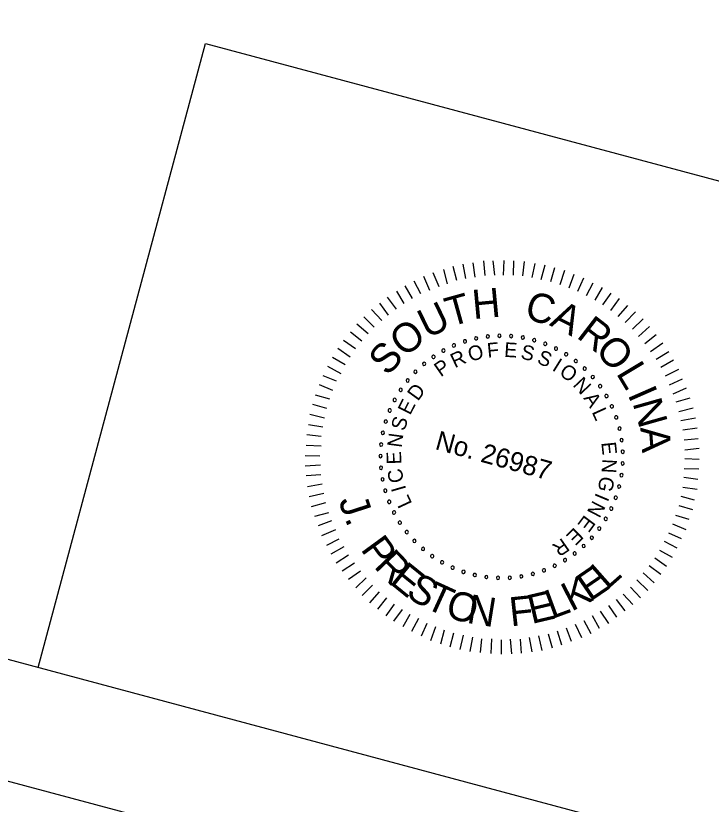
# Model space of a CAD drawing. Extents: x 1970764 to 1971371, y 795839 to 796297.
# Drawn here: x 1971092.8 to 1971137.2, y 795889.2 to 795939.6 of the extents above; entities that cross this region are included whole.
import ezdxf

# ---------------------------------------------------------------- set-up
doc = ezdxf.new("R2010")
doc.units = 0
for name, color, linetype in [('BR_BORDER LINES', 7, 'Continuous'), ('BR_TEXT', 7, 'Continuous'), ('Level 31', 7, 'Continuous')]:
    doc.layers.add(name, color=color, linetype=linetype)

msp = doc.modelspace()

# ---------------------------------------------------------------- linework, layer by layer
at = {"layer": 'BR_BORDER LINES'}
for p, q in [((1970792.881, 795978.637), (1971280.696, 795848.052)), ((1971094.278, 795897.955), (1971104.945, 795937.803)), ((1971104.945, 795937.803), (1971182.685, 795916.993))]:
    msp.add_line(p, q, dxfattribs=at)
at = {"layer": 'BR_TEXT'}
for p, q in [((1971120.999, 795922.662), (1971120.769, 795923.567)), ((1971121.568, 795922.786), (1971121.406, 795923.699)), ((1971122.17, 795922.886), (1971122.045, 795923.789)), ((1971122.796, 795922.98), (1971122.72, 795923.91)), ((1971123.419, 795923.009), (1971123.326, 795923.929)), ((1971123.981, 795923.013), (1971124.026, 795923.949)), ((1971124.618, 795922.997), (1971124.643, 795923.912)), ((1971125.219, 795922.951), (1971125.326, 795923.869)), ((1971125.807, 795922.856), (1971125.988, 795923.753)), ((1971126.388, 795922.735), (1971126.646, 795923.665)), ((1971127.006, 795922.604), (1971127.253, 795923.497)), ((1971119.862, 795922.269), (1971119.494, 795923.159)), ((1971120.395, 795922.456), (1971120.164, 795923.361)), ((1971127.604, 795922.399), (1971127.886, 795923.322)), ((1971128.176, 795922.2), (1971128.482, 795923.064)), ((1971118.704, 795921.801), (1971118.275, 795922.614)), ((1971119.276, 795922.031), (1971118.891, 795922.912)), ((1971128.718, 795921.984), (1971129.11, 795922.823)), ((1971129.27, 795921.71), (1971129.705, 795922.512)), ((1971118.173, 795921.521), (1971117.703, 795922.332)), ((1971129.824, 795921.397), (1971130.292, 795922.216)), ((1971117.14, 795920.831), (1971116.575, 795921.589)), ((1971117.627, 795921.191), (1971117.162, 795921.974)), ((1971130.317, 795921.101), (1971130.857, 795921.846)), ((1971130.836, 795920.756), (1971131.38, 795921.515)), ((1971116.635, 795920.45), (1971116.073, 795921.22)), ((1971131.288, 795920.364), (1971131.908, 795921.061)), ((1971116.208, 795920.115), (1971115.556, 795920.802)), ((1971131.741, 795919.972), (1971132.41, 795920.655)), ((1971115.712, 795919.677), (1971115.058, 795920.352)), ((1971132.215, 795919.56), (1971132.89, 795920.215)), ((1971115.327, 795919.25), (1971114.618, 795919.873)), ((1971132.603, 795919.08), (1971133.303, 795919.727)), ((1971114.931, 795918.785), (1971114.2, 795919.374)), ((1971133.001, 795918.635), (1971133.724, 795919.223)), ((1971114.529, 795918.295), (1971113.771, 795918.838)), ((1971133.369, 795918.133), (1971134.151, 795918.692)), ((1971114.194, 795917.76), (1971113.39, 795918.329)), ((1971133.729, 795917.646), (1971134.527, 795918.12)), ((1971113.876, 795917.287), (1971113.054, 795917.741)), ((1971134.028, 795917.136), (1971134.824, 795917.597)), ((1971113.609, 795916.706), (1971112.765, 795917.18)), ((1971134.314, 795916.576), (1971135.165, 795916.995)), ((1971113.316, 795916.226), (1971112.466, 795916.582)), ((1971113.089, 795915.648), (1971112.224, 795915.994)), ((1971134.584, 795916.007), (1971135.408, 795916.38)), ((1971134.798, 795915.427), (1971135.663, 795915.802)), ((1971112.894, 795915.088), (1971111.964, 795915.345)), ((1971135.003, 795914.916), (1971135.891, 795915.178)), ((1971112.705, 795914.499), (1971111.799, 795914.75)), ((1971135.179, 795914.294), (1971136.075, 795914.54)), ((1971112.558, 795913.872), (1971111.621, 795914.104)), ((1971112.441, 795913.303), (1971111.517, 795913.439)), ((1971135.302, 795913.725), (1971136.243, 795913.892)), ((1971135.415, 795913.12), (1971136.334, 795913.253)), ((1971112.338, 795912.691), (1971111.419, 795912.798)), ((1971135.509, 795912.493), (1971136.413, 795912.576)), ((1971112.329, 795912.079), (1971111.369, 795912.131)), ((1971135.546, 795911.855), (1971136.466, 795911.947)), ((1971112.26, 795911.443), (1971111.321, 795911.476)), ((1971135.551, 795911.293), (1971136.477, 795911.263)), ((1971112.286, 795910.862), (1971111.308, 795910.799)), ((1971135.507, 795910.65), (1971136.437, 795910.633)), ((1971112.305, 795910.256), (1971111.376, 795910.179)), ((1971135.487, 795910.095), (1971136.373, 795909.97)), ((1971112.406, 795909.654), (1971111.465, 795909.487)), ((1971135.421, 795909.472), (1971136.33, 795909.327)), ((1971112.51, 795909.064), (1971111.572, 795908.856)), ((1971135.288, 795908.894), (1971136.157, 795908.654)), ((1971112.611, 795908.462), (1971111.703, 795908.219)), ((1971135.161, 795908.289), (1971136.041, 795908.045)), ((1971112.811, 795907.832), (1971111.902, 795907.589)), ((1971134.952, 795907.679), (1971135.814, 795907.413)), ((1971113.004, 795907.324), (1971112.137, 795906.99)), ((1971134.772, 795907.127), (1971135.623, 795906.772)), ((1971113.242, 795906.738), (1971112.365, 795906.366)), ((1971134.509, 795906.559), (1971135.327, 795906.186)), ((1971113.469, 795906.154), (1971112.671, 795905.734)), ((1971134.227, 795906.023), (1971135.041, 795905.584)), ((1971113.787, 795905.665), (1971112.961, 795905.186)), ((1971133.935, 795905.449), (1971134.745, 795904.998)), ((1971114.089, 795905.114), (1971113.296, 795904.613)), ((1971133.638, 795904.957), (1971134.384, 795904.417)), ((1971114.458, 795904.612), (1971113.686, 795904.091)), ((1971133.285, 795904.453), (1971134.018, 795903.917)), ((1971114.839, 795904.106), (1971114.076, 795903.569)), ((1971132.89, 795903.988), (1971133.599, 795903.365)), ((1971115.2, 795903.672), (1971114.544, 795903.039)), ((1971132.485, 795903.539), (1971133.196, 795902.875)), ((1971115.619, 795903.209), (1971114.956, 795902.551)), ((1971132.077, 795903.078), (1971132.719, 795902.406)), ((1971116.036, 795902.786), (1971115.428, 795902.086)), ((1971116.501, 795902.391), (1971115.931, 795901.68)), ((1971131.606, 795902.634), (1971132.236, 795901.965)), ((1971116.991, 795901.988), (1971116.454, 795901.255)), ((1971130.686, 795901.913), (1971131.198, 795901.157)), ((1971131.168, 795902.301), (1971131.727, 795901.572)), ((1971117.514, 795901.657), (1971116.957, 795900.902)), ((1971117.987, 795901.339), (1971117.551, 795900.538)), ((1971130.156, 795901.539), (1971130.673, 795900.755)), ((1971118.555, 795901.075), (1971118.096, 795900.24)), ((1971129.114, 795900.959), (1971129.548, 795900.118)), ((1971129.643, 795901.28), (1971130.082, 795900.451)), ((1971119.08, 795900.756), (1971118.711, 795899.95)), ((1971119.634, 795900.536), (1971119.325, 795899.66)), ((1971120.195, 795900.341), (1971119.948, 795899.447)), ((1971127.977, 795900.472), (1971128.306, 795899.633)), ((1971128.552, 795900.714), (1971128.946, 795899.87)), ((1971120.792, 795900.136), (1971120.548, 795899.254)), ((1971121.411, 795900.005), (1971121.188, 795899.104)), ((1971122.004, 795899.881), (1971121.819, 795898.97)), ((1971125.62, 795899.869), (1971125.794, 795898.953)), ((1971126.21, 795899.973), (1971126.433, 795899.043)), ((1971126.835, 795900.107), (1971127.078, 795899.199)), ((1971127.408, 795900.296), (1971127.682, 795899.406)), ((1971122.579, 795899.788), (1971122.495, 795898.903)), ((1971123.207, 795899.788), (1971123.158, 795898.84)), ((1971123.83, 795899.723), (1971123.817, 795898.805)), ((1971124.411, 795899.749), (1971124.488, 795898.819)), ((1971125.03, 795899.765), (1971125.114, 795898.86))]:
    msp.add_line(p, q, dxfattribs=at)
for centre, start, end in [((1971122.235, 795918.966), 12.2328, 192.2328), ((1971122.235, 795918.966), 192.2328, 12.2328), ((1971122.973, 795919.087), 6.6943, 186.6943), ((1971122.973, 795919.087), 186.6943, 6.6943), ((1971123.718, 795919.137), 1.1559, 181.1559), ((1971123.718, 795919.137), 181.1559, 1.1559), ((1971124.465, 795919.114), 175.6174, 355.6174), ((1971124.465, 795919.114), 355.6174, 175.6174), ((1971125.207, 795919.02), 170.079, 350.079), ((1971125.207, 795919.02), 350.079, 170.079), ((1971125.936, 795918.854), 344.5405, 164.5405), ((1971120.812, 795918.513), 23.3097, 203.3097), ((1971120.812, 795918.513), 203.3097, 23.3097), ((1971121.513, 795918.774), 17.7713, 197.7713), ((1971121.513, 795918.774), 197.7713, 17.7713), ((1971125.936, 795918.854), 164.5405, 344.5405), ((1971126.645, 795918.619), 159.002, 339.002), ((1971126.645, 795918.619), 339.002, 159.002), ((1971120.14, 795918.185), 28.8482, 208.8482), ((1971120.14, 795918.185), 208.8482, 28.8482), ((1971127.329, 795918.316), 153.4636, 333.4636), ((1971127.329, 795918.316), 333.4636, 153.4636), ((1971127.98, 795917.949), 147.9251, 327.9251), ((1971127.98, 795917.949), 327.9251, 147.9251), ((1971118.906, 795917.345), 39.9251, 219.9251), ((1971119.503, 795917.795), 34.3866, 214.3866), ((1971119.503, 795917.795), 214.3866, 34.3866), ((1971128.592, 795917.521), 142.3866, 322.3866), ((1971128.592, 795917.521), 322.3866, 142.3866), ((1971118.356, 795916.839), 45.4636, 225.4636), ((1971118.906, 795917.345), 219.9251, 39.9251), ((1971129.161, 795917.035), 136.8482, 316.8482), ((1971129.161, 795917.035), 316.8482, 136.8482), ((1971118.356, 795916.839), 225.4636, 45.4636), ((1971129.68, 795916.497), 131.3097, 311.3097), ((1971129.68, 795916.497), 311.3097, 131.3097), ((1971117.857, 795916.282), 51.002, 231.002), ((1971117.857, 795916.282), 231.002, 51.002), ((1971130.144, 795915.912), 125.7713, 305.7713), ((1971130.144, 795915.912), 305.7713, 125.7713), ((1971117.414, 795915.68), 56.5405, 236.5405), ((1971117.414, 795915.68), 236.5405, 56.5405), ((1971117.031, 795915.038), 62.079, 242.079), ((1971117.031, 795915.038), 242.079, 62.079), ((1971130.55, 795915.284), 120.2328, 300.2328), ((1971130.55, 795915.284), 300.2328, 120.2328), ((1971116.712, 795914.362), 67.6174, 247.6174), ((1971116.712, 795914.362), 247.6174, 67.6174), ((1971130.894, 795914.62), 114.6943, 294.6943), ((1971130.894, 795914.62), 294.6943, 114.6943), ((1971131.171, 795913.926), 109.1559, 289.1559), ((1971131.171, 795913.926), 289.1559, 109.1559), ((1971116.46, 795913.659), 73.1559, 253.1559), ((1971116.46, 795913.659), 253.1559, 73.1559), ((1971116.277, 795912.934), 78.6943, 258.6943), ((1971116.277, 795912.934), 258.6943, 78.6943), ((1971131.381, 795913.209), 103.6174, 283.6174), ((1971131.381, 795913.209), 283.6174, 103.6174), ((1971131.52, 795912.474), 98.079, 278.079), ((1971131.52, 795912.474), 278.079, 98.079), ((1971116.164, 795912.195), 84.2328, 264.2328), ((1971116.164, 795912.195), 264.2328, 84.2328), ((1971116.124, 795911.449), 89.7713, 269.7713), ((1971116.124, 795911.449), 269.7713, 89.7713), ((1971131.588, 795911.73), 92.5405, 272.5405), ((1971131.588, 795911.73), 272.5405, 92.5405), ((1971131.583, 795910.983), 87.002, 267.002), ((1971131.583, 795910.983), 267.002, 87.002), ((1971116.155, 795910.702), 95.3097, 275.3097), ((1971116.155, 795910.702), 275.3097, 95.3097), ((1971116.259, 795909.962), 100.8482, 280.8482), ((1971116.259, 795909.962), 280.8482, 100.8482), ((1971131.507, 795910.239), 81.4636, 261.4636), ((1971131.507, 795910.239), 261.4636, 81.4636), ((1971131.359, 795909.506), 75.9251, 255.9251), ((1971131.359, 795909.506), 255.9251, 75.9251), ((1971116.433, 795909.235), 106.3866, 286.3866), ((1971116.433, 795909.235), 286.3866, 106.3866), ((1971131.141, 795908.791), 70.3866, 250.3866), ((1971131.141, 795908.791), 250.3866, 70.3866), ((1971116.677, 795908.528), 111.9251, 291.9251), ((1971116.677, 795908.528), 291.9251, 111.9251), ((1971116.988, 795907.849), 117.4636, 297.4636), ((1971116.988, 795907.849), 297.4636, 117.4636), ((1971130.855, 795908.101), 64.8482, 244.8482), ((1971130.855, 795908.101), 244.8482, 64.8482), ((1971130.503, 795907.441), 59.3097, 239.3097), ((1971130.503, 795907.441), 239.3097, 59.3097), ((1971117.363, 795907.202), 123.002, 303.002), ((1971117.363, 795907.202), 303.002, 123.002), ((1971130.09, 795906.818), 53.7713, 233.7713), ((1971130.09, 795906.818), 233.7713, 53.7713), ((1971117.799, 795906.595), 128.5405, 308.5405), ((1971117.799, 795906.595), 308.5405, 128.5405), ((1971118.291, 795906.032), 134.079, 314.079), ((1971118.291, 795906.032), 314.079, 134.079), ((1971129.618, 795906.238), 48.2328, 228.2328), ((1971129.618, 795906.238), 228.2328, 48.2328), ((1971118.836, 795905.52), 139.6174, 319.6174), ((1971118.836, 795905.52), 319.6174, 139.6174), ((1971129.093, 795905.707), 42.6943, 222.6943), ((1971129.093, 795905.707), 222.6943, 42.6943), ((1971119.427, 795905.063), 145.1559, 325.1559), ((1971119.427, 795905.063), 325.1559, 145.1559), ((1971127.901, 795904.807), 31.6174, 211.6174), ((1971127.901, 795904.807), 211.6174, 31.6174), ((1971128.519, 795905.228), 37.1559, 217.1559), ((1971128.519, 795905.228), 217.1559, 37.1559), ((1971120.059, 795904.664), 150.6943, 330.6943), ((1971120.059, 795904.664), 330.6943, 150.6943), ((1971120.727, 795904.329), 156.2328, 336.2328), ((1971120.727, 795904.329), 336.2328, 156.2328), ((1971127.246, 795904.448), 26.079, 206.079), ((1971127.246, 795904.448), 206.079, 26.079), ((1971121.425, 795904.06), 161.7713, 341.7713), ((1971121.425, 795904.06), 341.7713, 161.7713), ((1971122.145, 795903.859), 167.3097, 347.3097), ((1971122.145, 795903.859), 347.3097, 167.3097), ((1971125.116, 795903.77), 9.4636, 189.4636), ((1971125.847, 795903.927), 15.002, 195.002), ((1971125.847, 795903.927), 195.002, 15.002), ((1971126.559, 795904.153), 20.5405, 200.5405), ((1971126.559, 795904.153), 200.5405, 20.5405), ((1971122.881, 795903.729), 352.8482, 172.8482), ((1971122.881, 795903.729), 172.8482, 352.8482), ((1971123.626, 795903.67), 358.3866, 178.3866), ((1971123.626, 795903.67), 178.3866, 358.3866), ((1971124.373, 795903.684), 3.9251, 183.9251), ((1971124.373, 795903.684), 183.9251, 3.9251), ((1971125.116, 795903.77), 189.4636, 9.4636)]:
    msp.add_arc(centre, 0.105, start, end, dxfattribs=at)
at = {"layer": 'Level 31'}
msp.add_lwpolyline([(1970764.378, 795978.504), (1971286.011, 795838.866), (1971371.345, 796157.642), (1970849.712, 796297.279)], close=True, dxfattribs=at)

# ---------------------------------------------------------------- texts
at = {"layer": 'BR_TEXT'}
for s, height, rotation, p in [('H', 1.861, 5.3774, (1971122.056, 795920.192)), ('T', 1.861, 15.5129, (1971120.56, 795919.699)), ('C', 1.861, 344.5619, (1971125.245, 795920.244)), ('U', 1.861, 25.8159, (1971119.094, 795918.931)), ('A', 1.861, 333.2118, (1971126.862, 795919.823)), ('O', 1.861, 37.0404, (1971117.61, 795917.714)), ('R', 1.861, 322.4481, (1971128.571, 795919.057)), ('O', 1.859, 311.6005, (1971129.765, 795918.167)), ('S', 1.859, 48.2648, (1971116.582, 795916.505)), ('O', 0.934, 15.8614, (1971121.854, 795917.468)), ('F', 0.934, 5.6264, (1971122.969, 795917.729)), ('E', 0.934, 356.424, (1971123.998, 795917.79)), ('S', 0.934, 347.2216, (1971125.023, 795917.686)), ('R', 0.934, 25.4086, (1971120.87, 795917.05)), ('S', 0.934, 337.6745, (1971126.055, 795917.407)), ('P', 0.934, 34.9557, (1971119.969, 795916.474)), ('I', 0.934, 328.1273, (1971127.026, 795916.96)), ('L', 1.861, 300.9625, (1971131.133, 795916.748)), ('O', 0.934, 323.4528, (1971127.471, 795916.684)), ('N', 0.934, 313.2178, (1971128.358, 795915.959)), ('D', 0.934, 54.0501, (1971118.513, 795914.919)), ('I', 1.861, 293.6749, (1971131.879, 795915.395)), ('E', 0.934, 63.2525, (1971118.014, 795914.017)), ('A', 0.934, 303.6706, (1971129.057, 795915.15)), ('N', 1.861, 285.7173, (1971132.208, 795914.85)), ('L', 0.934, 294.4683, (1971129.595, 795914.271)), ('S', 0.934, 72.7996, (1971117.656, 795913.01)), ('No. 26987', 1.2262, 344.5405, (1971119.551, 795911.906)), ('A', 1.861, 274.4929, (1971132.706, 795913.273)), ('N', 0.934, 82.3468, (1971117.47, 795911.957)), ('E', 0.934, 276.0627, (1971130.218, 795912.314)), ('E', 0.934, 91.5492, (1971117.458, 795910.927)), ('N', 0.934, 266.8603, (1971130.288, 795911.285)), ('C', 0.934, 101.4403, (1971117.629, 795909.833)), ('G', 0.934, 257.3131, (1971130.185, 795910.221)), ('I', 0.934, 106.1147, (1971117.775, 795909.33)), ('L', 0.934, 114.9732, (1971118.162, 795908.416)), ('I', 0.934, 247.422, (1971129.894, 795909.153)), ('J', 1.853, 287.9696, (1971113.435, 795908.619)), ('N', 0.934, 242.7476, (1971129.693, 795908.669)), ('.', 1.853, 294.411, (1971113.81, 795907.463)), ('E', 0.934, 233.2004, (1971129.165, 795907.74)), ('P', 1.853, 306.1171, (1971114.813, 795905.498)), ('E', 0.934, 223.998, (1971128.516, 795906.939)), ('R', 0.934, 214.7957, (1971127.748, 795906.252)), ('R', 1.853, 313.5496, (1971115.649, 795904.373)), ('E', 1.853, 320.982, (1971116.624, 795903.365)), ('E', 1.853, 34.3776, (1971129.49, 795902.118)), ('L', 1.853, 41.4384, (1971130.585, 795902.876)), ('S', 1.853, 328.0429, (1971117.663, 795902.532)), ('T', 1.853, 335.4753, (1971118.859, 795901.8)), ('K', 1.853, 27.3167, (1971128.31, 795901.5)), ('O', 1.853, 343.1555, (1971120.184, 795901.213)), ('E', 1.853, 13.1951, (1971125.768, 795900.721)), ('L', 1.853, 20.2559, (1971127.063, 795901.032)), ('N', 1.853, 350.8357, (1971121.575, 795900.809)), ('F', 1.853, 6.1342, (1971124.444, 795900.571))]:
    msp.add_text(s, height=height, rotation=rotation, dxfattribs=at).set_placement(p)

doc.saveas('drawing.dxf')
